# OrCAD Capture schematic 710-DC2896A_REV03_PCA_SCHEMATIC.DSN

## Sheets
1 PAGE1: size Custom; company: ANALOG DEVICES; note: DEMO BOARD BILL OF MATERIALS; note: MULTIPHASE BOOST CONVERTER EXPANDER WITH INTERNAL GATE DRIVERS
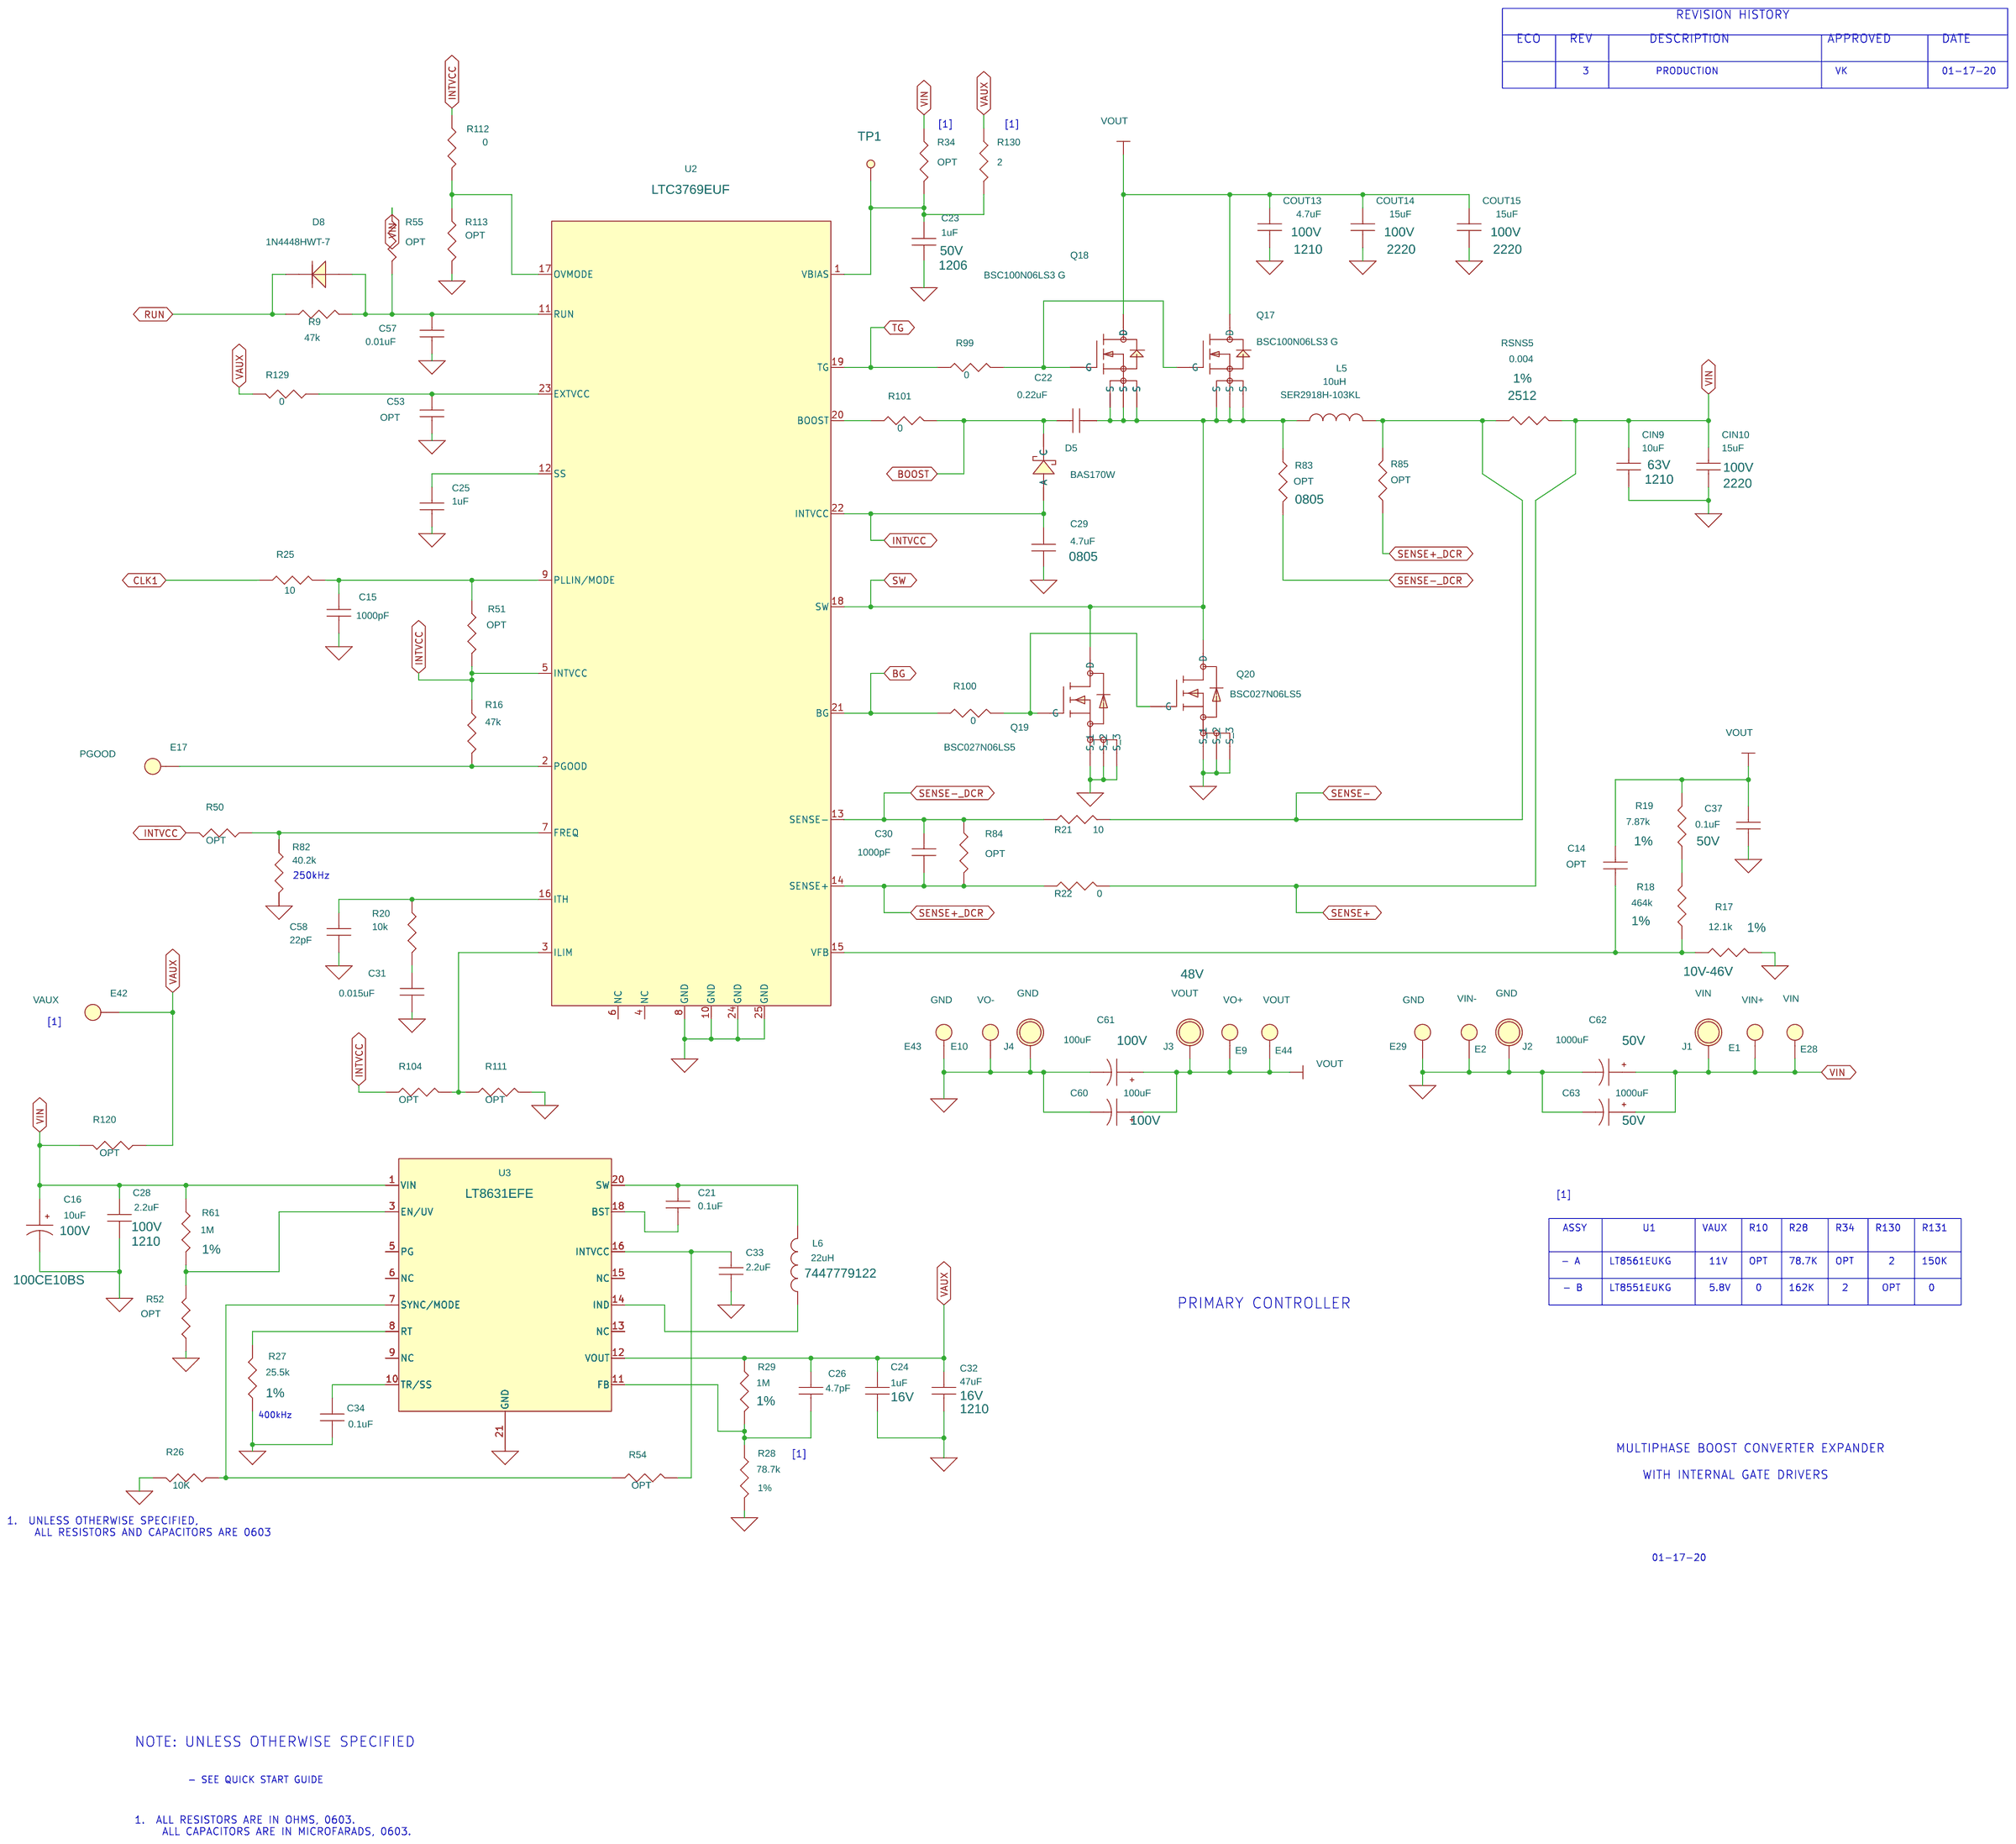
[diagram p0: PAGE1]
2 PAGE2: size Custom
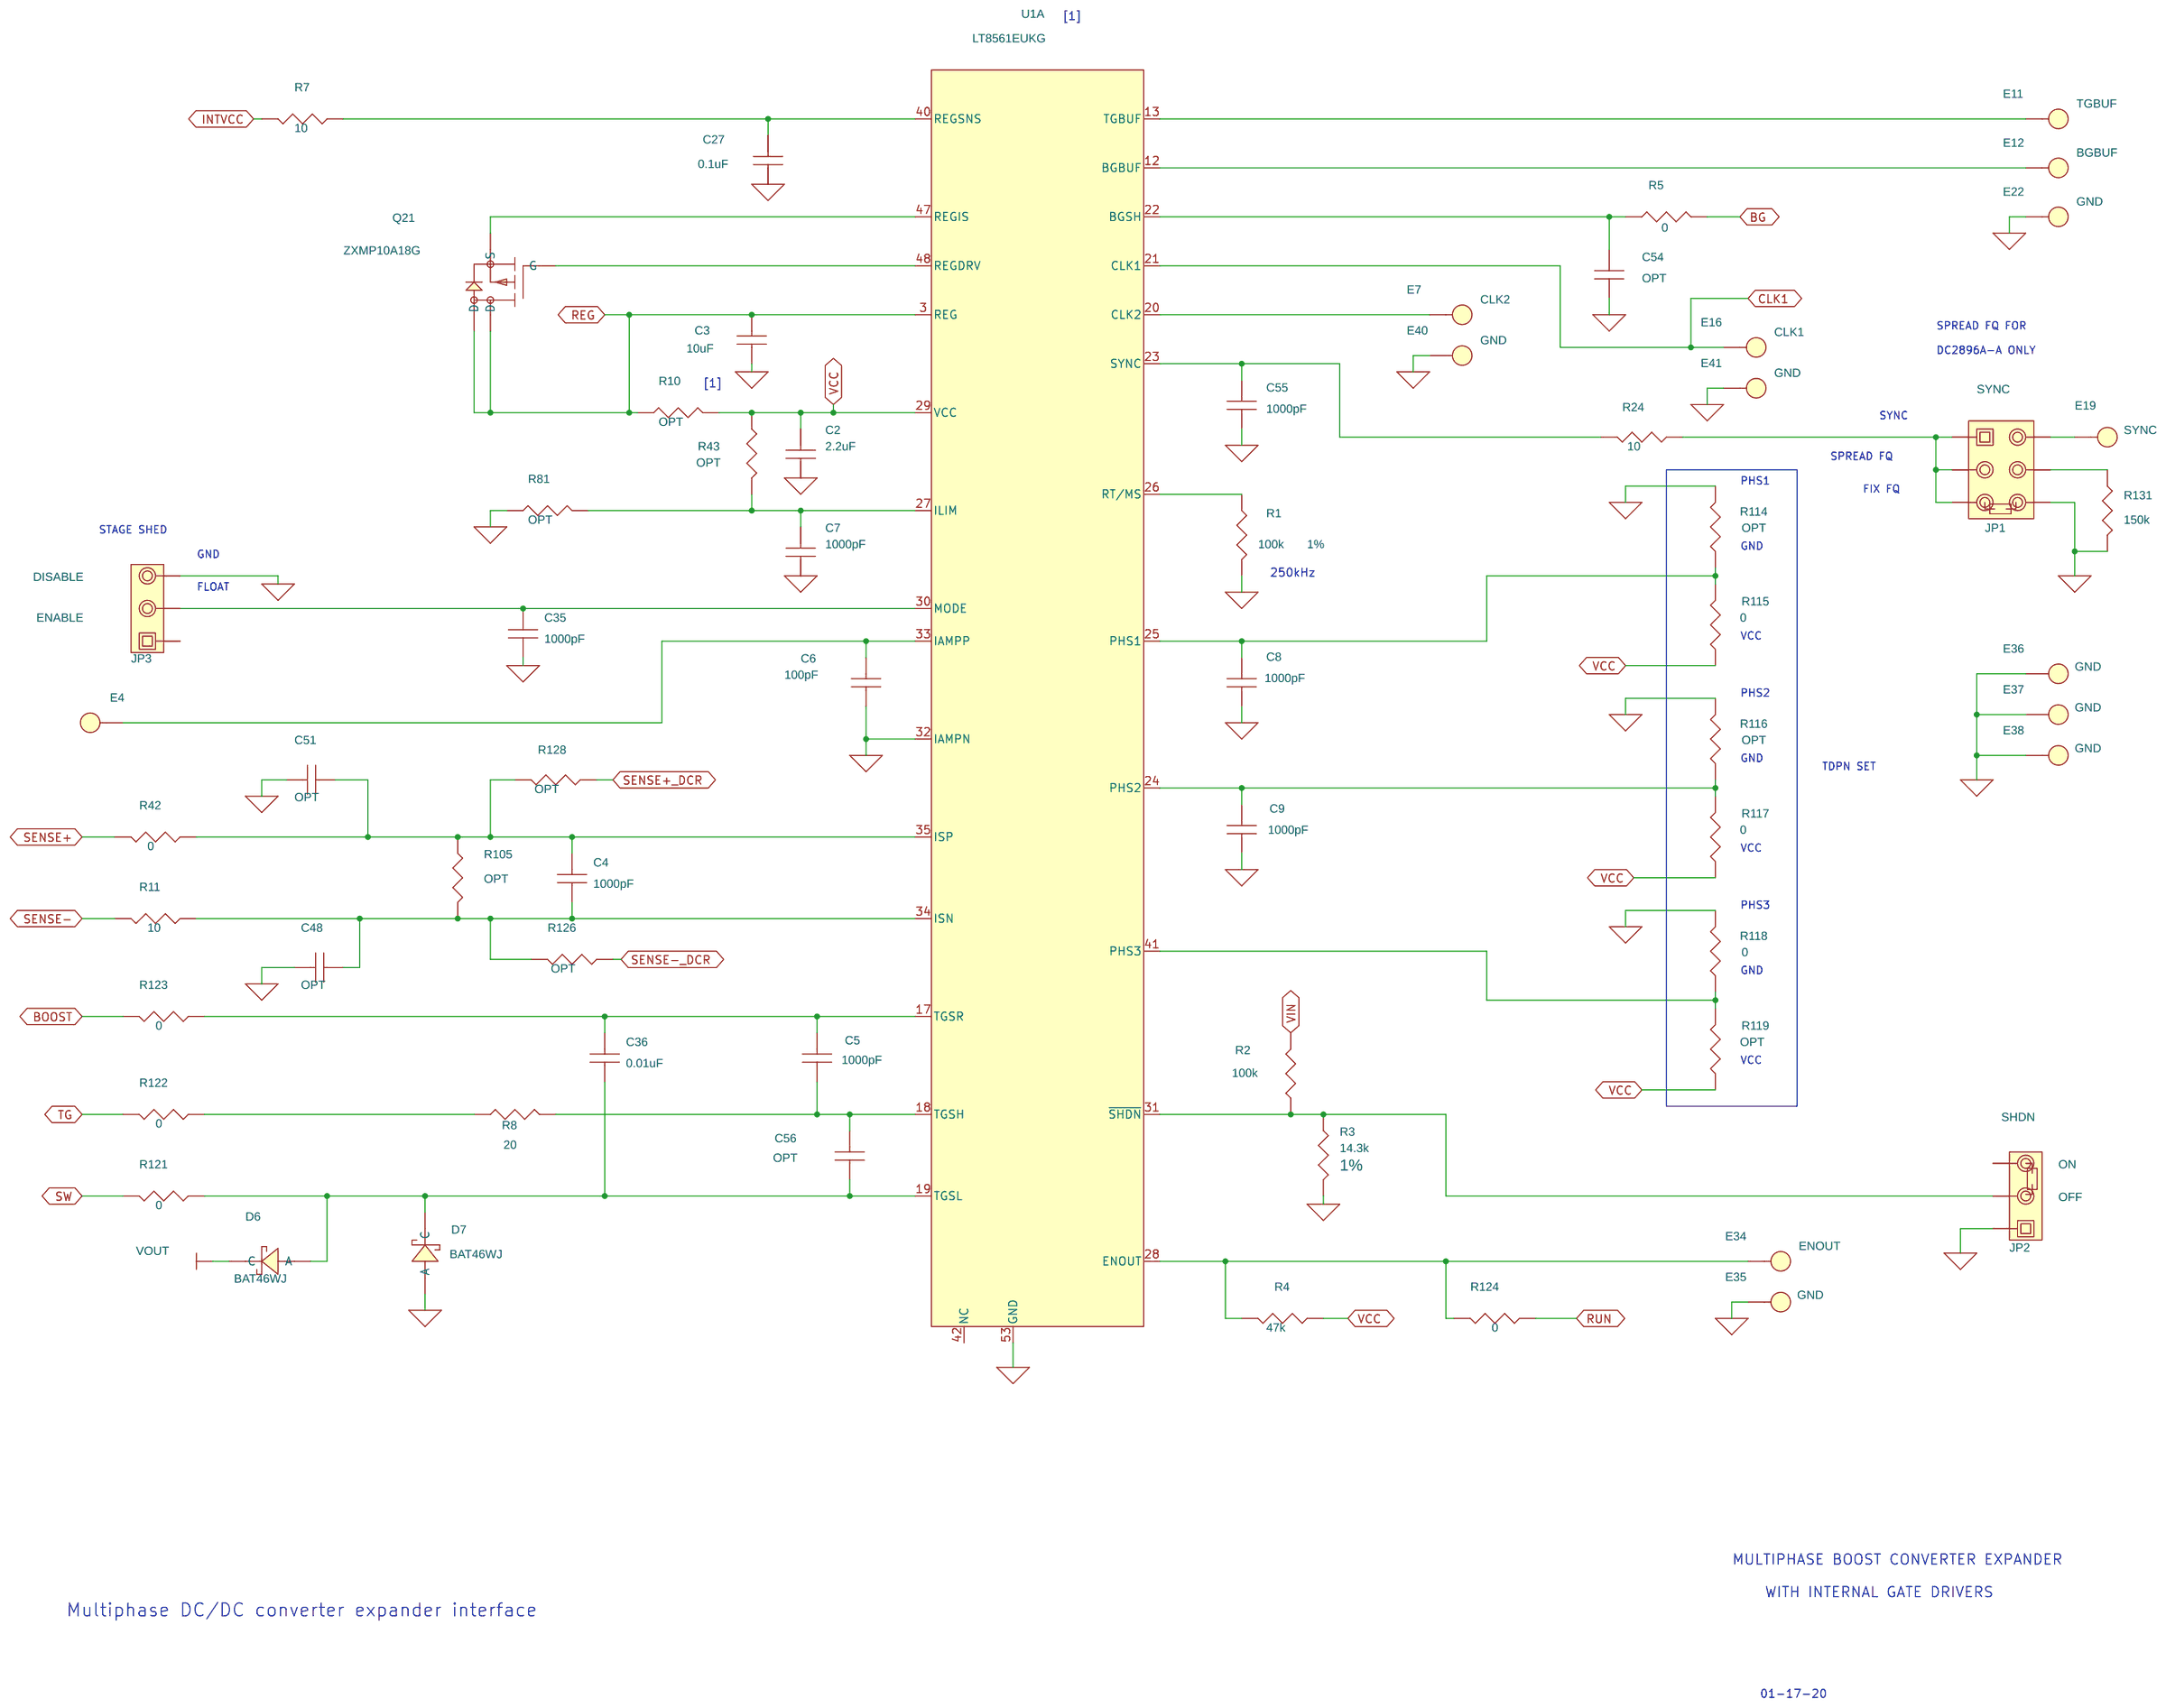
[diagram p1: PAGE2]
3 PAGE4: size Custom
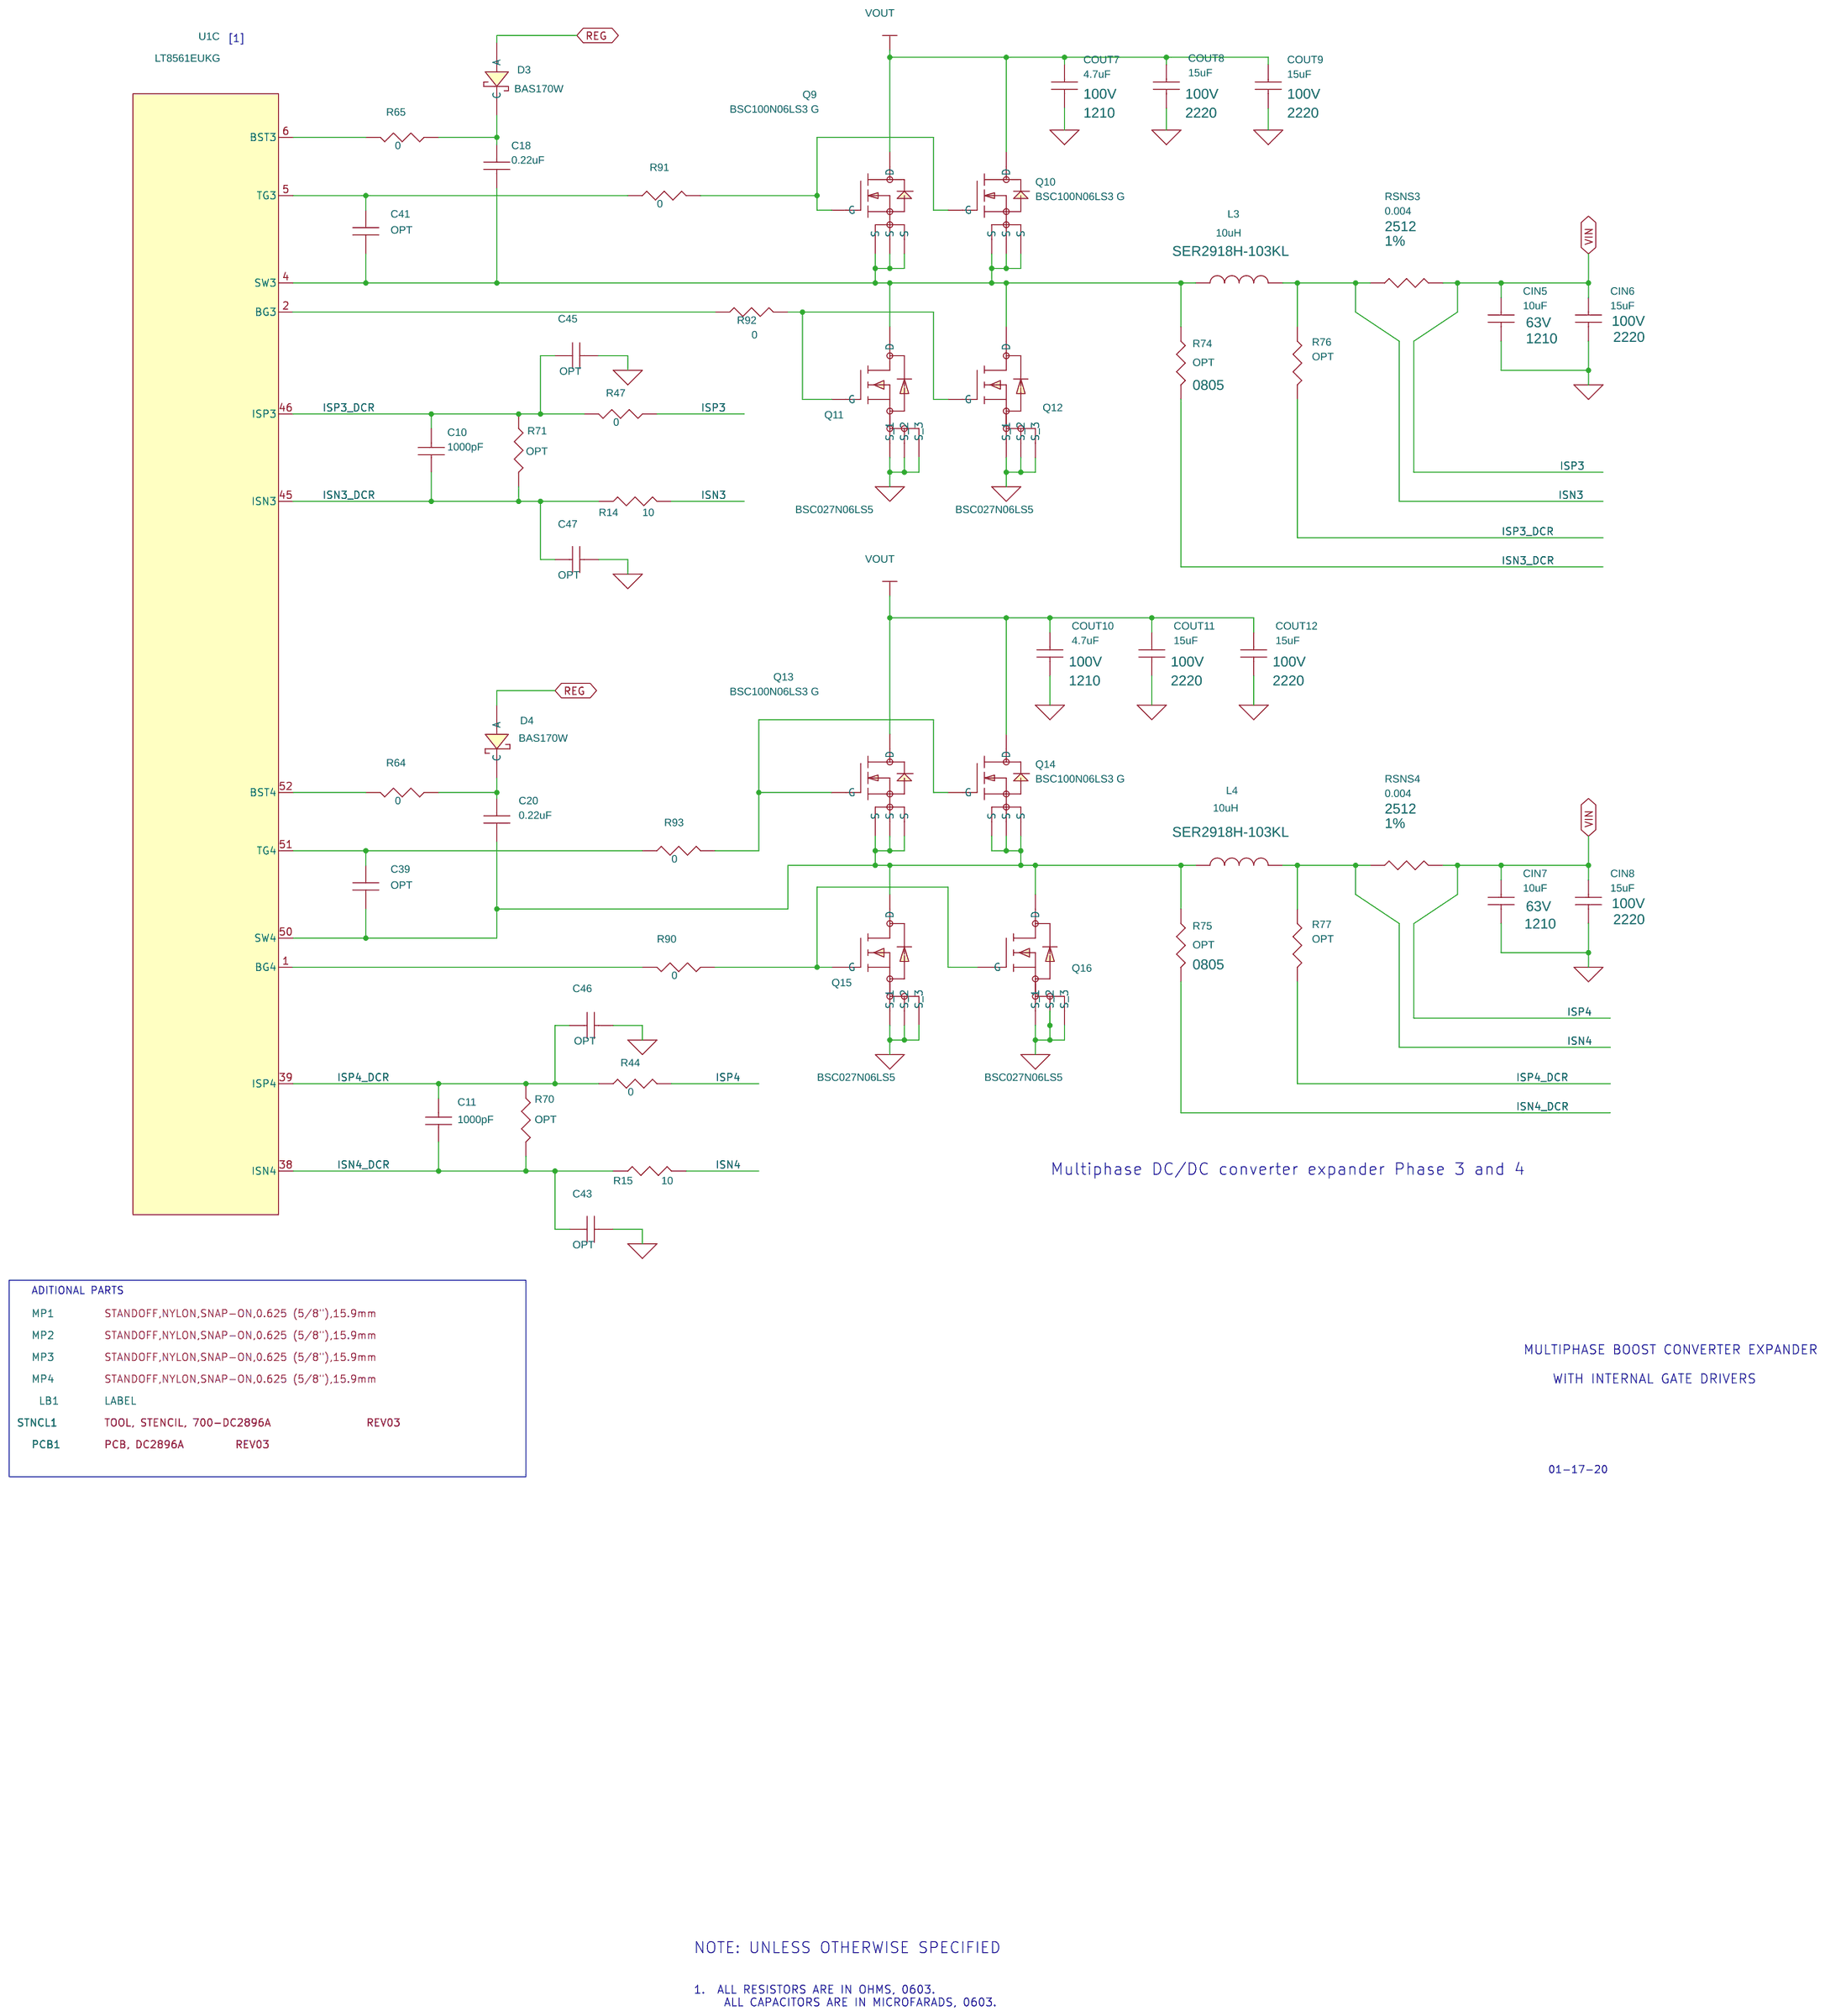
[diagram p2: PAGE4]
4 PAGE3: size Custom
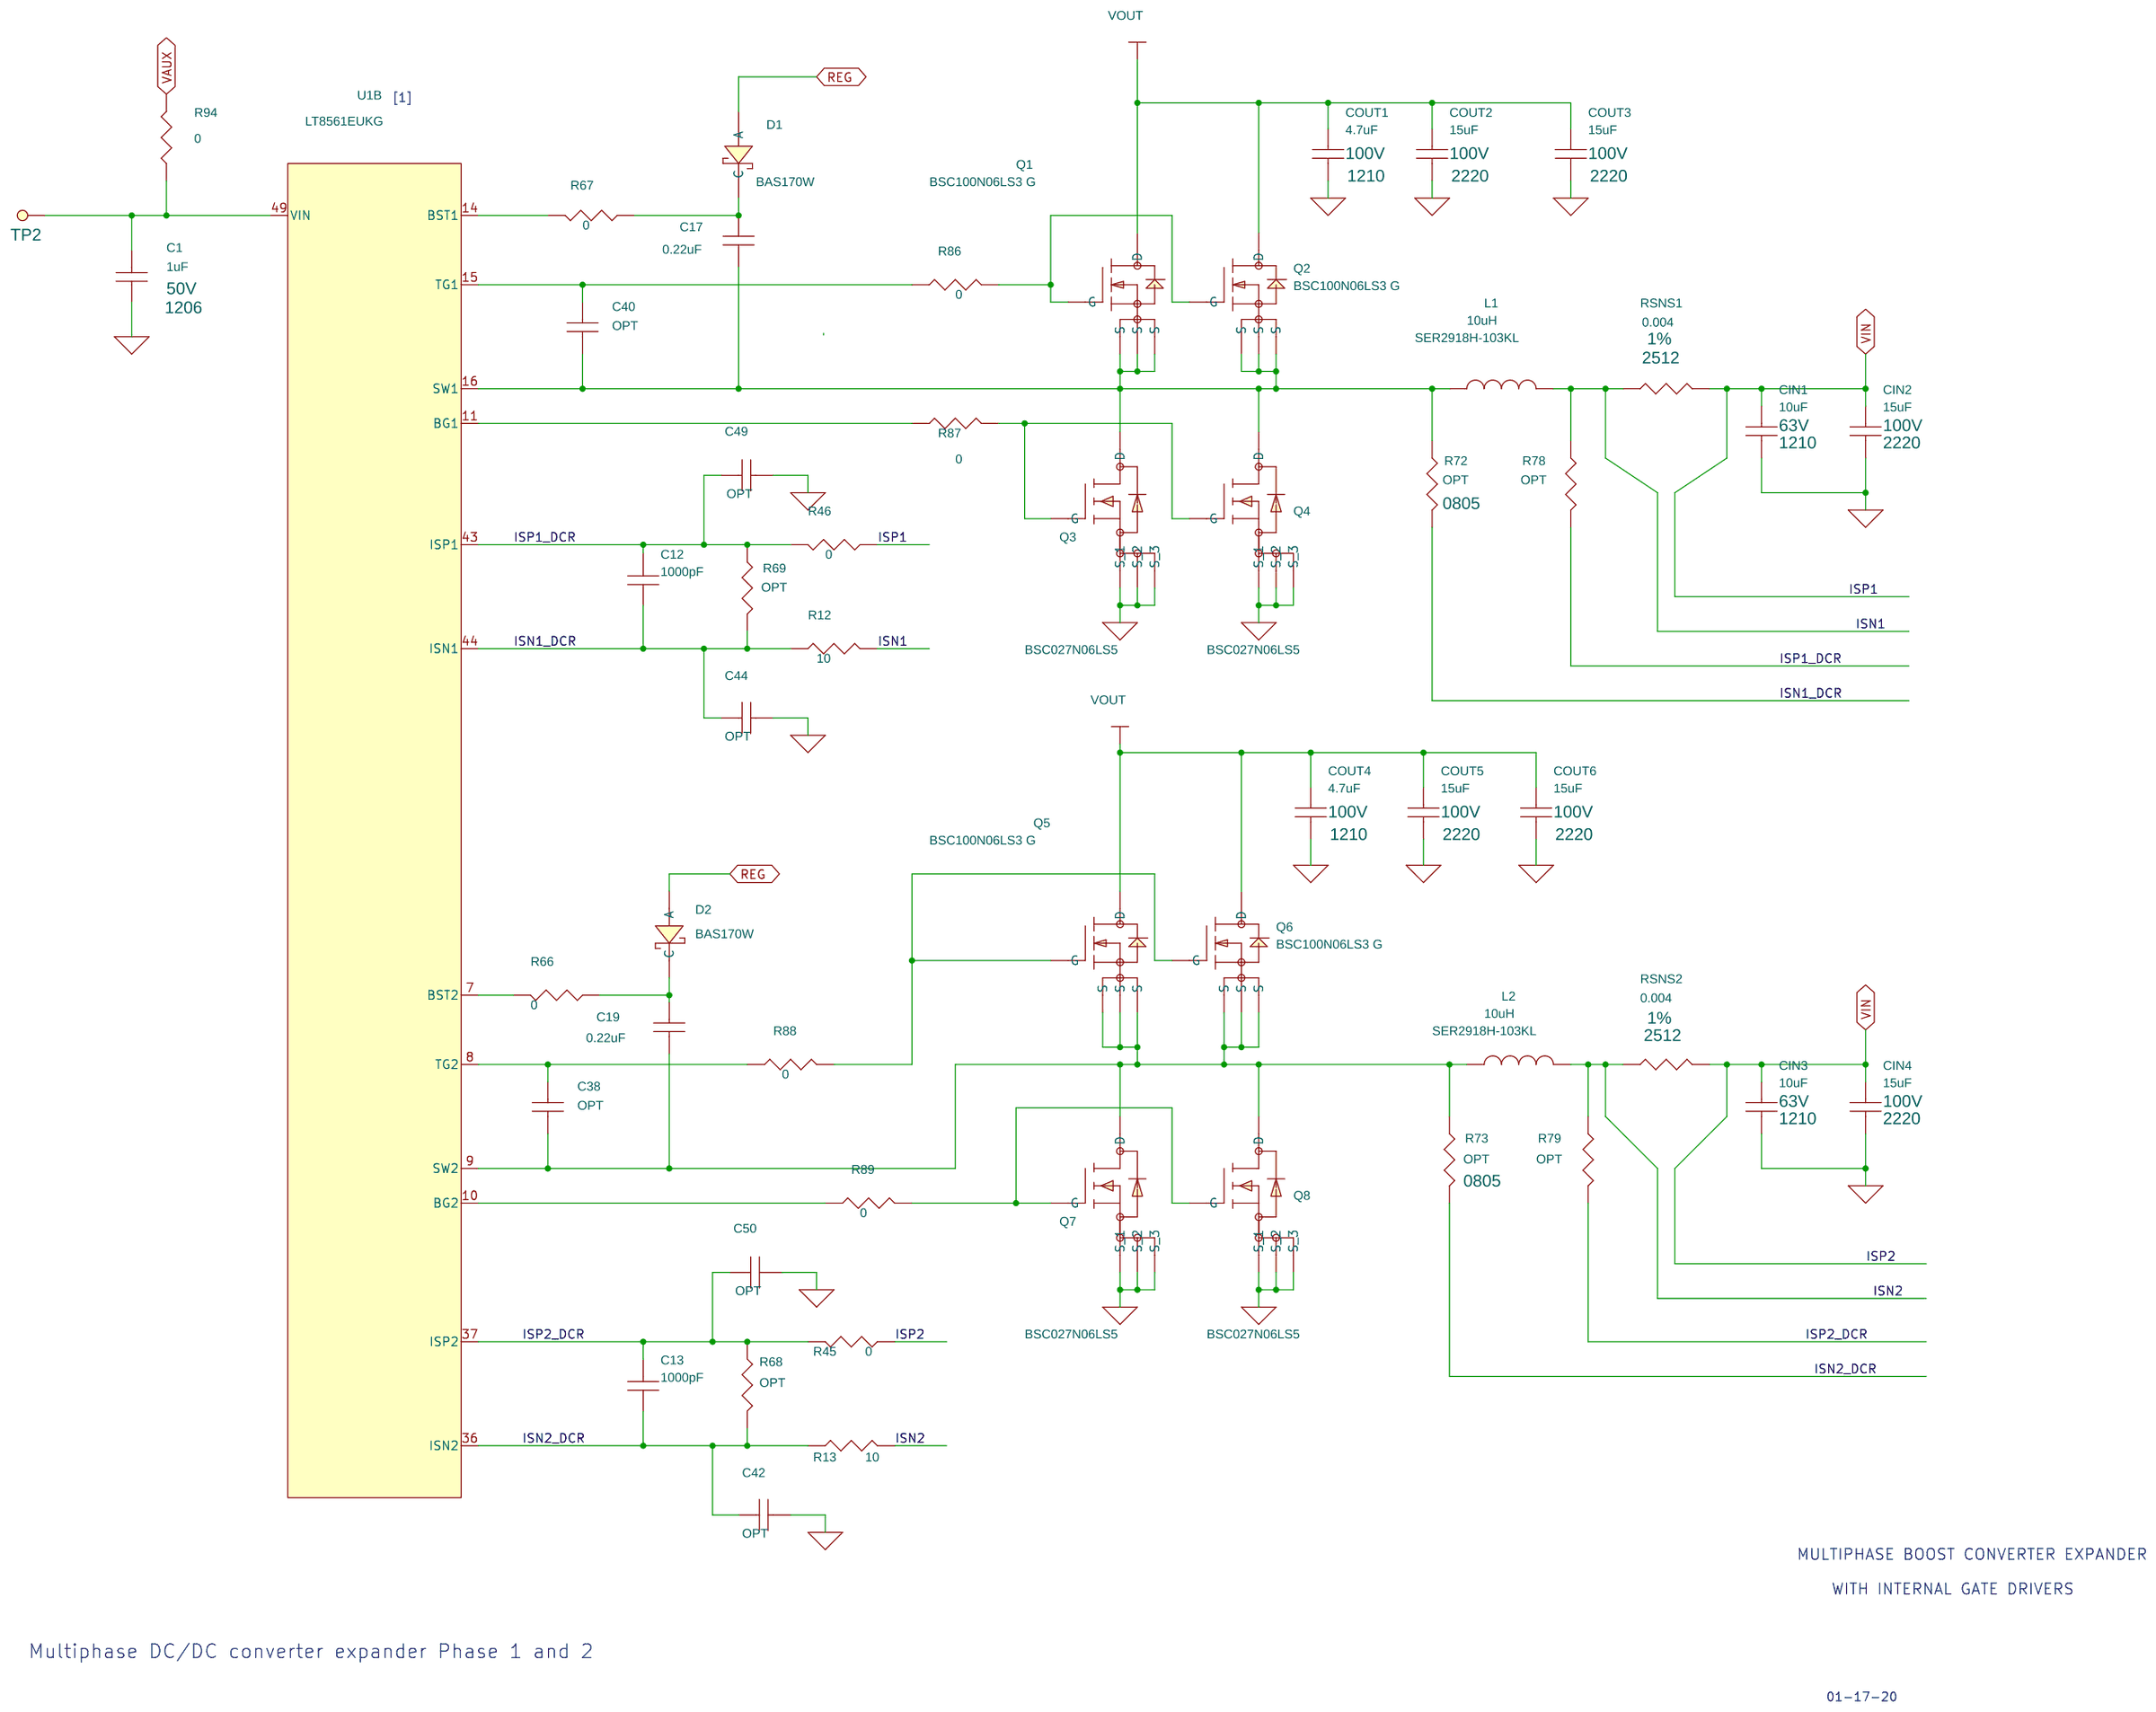
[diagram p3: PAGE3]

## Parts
sheet PAGE1
C14  OPT  [CC0603N]
C15  1000pF  [CC0603N]
C16  10uF  [SUNCON_CE-BS_6.3X7.7]
C21  0.1uF  [CC0603N]
C22  0.22uF  [CC0603N]
C23  1uF  [CC1206N]
C24  1uF  [CC0603N]
C25  1uF  [CC0603N]
C26  4.7pF  [CC0603N]
C28  2.2uF  [CC1210N]
C29  4.7uF  [CC0805N]
C30  1000pF  [CC0603N]
C31  0.015uF  [CC0603N]
C32  47uF  [CC1210N]
C33  2.2uF  [CC0603N]
C34  0.1uF  [CC0603N]
C37  0.1uF  [CC0603N]
C53  OPT  [CC0603N]
C57  0.01uF  [CC0603N]
C58  22pF  [CC0603N]
C60  100uF  [SUNCON_CE-BS_16X16.5]
C61  100uF  [SUNCON_CE-BS_16X16.5]
C62  1000uF  [PANASONIC_FKV_16X16.5]
C63  1000uF  [PANASONIC_FKV_16X16.5]
CIN9  10uF  [CC1210N]
CIN10  15uF  [CC2220N]
COUT13  4.7uF  [CC1210N]
COUT14  15uF  [CC2220N]
COUT15  15uF  [CC2220N]
D5  BAS170W  [SOD-323N]
D8  1N4448HWT-7  [SOD-523N]
E1  TEST POINT  [MILLMAX2308]
E2  TEST POINT  [MILLMAX2308]
E9  TEST POINT  [MILLMAX2308]
E10  TEST POINT  [MILLMAX2308]
E17  TEST POINT  [MILLMAX2308]
E28  TEST POINT  [MILLMAX2308]
E29  TEST POINT  [MILLMAX2308]
E42  TEST POINT  [MILLMAX2308]
E43  TEST POINT  [MILLMAX2308]
E44  TEST POINT  [MILLMAX2308]
J1  STUD,#10-32  [PENN-KFH-032]
J2  STUD,#10-32  [PENN-KFH-032]
J3  STUD,#10-32  [PENN-KFH-032]
J4  STUD,#10-32  [PENN-KFH-032]
L5  10uH  [COILCRAFT-SER2900]
L6  22uH  [WURTH-7345]
Q17  BSC100N06LS3 G  [INFINEON-PG-TDSON-8]
Q18  BSC100N06LS3 G  [INFINEON-PG-TDSON-8]
Q19  BSC027N06LS5  [INFINEON-PG-TDSON-8]
Q20  BSC027N06LS5  [INFINEON-PG-TDSON-8]
R9  47k  [CR0603N]
R16  47k  [CR0603N]
R17  12.1k  [CR0603N]
R18  464k  [CR0603N]
R19  7.87k  [CR0603N]
R20  10k  [CR0603N]
R21  10  [CR0603N]
R22  0  [CR0603N]
R25  10  [CR0603N]
R26  10K  [CR0603N]
R27  25.5k  [CR0603N]
R28  78.7k  [CR0603N]
R29  1M  [CR0603N]
R34  OPT  [CR0603N]
R50  OPT  [CR0603N]
R51  OPT  [CR0603N]
R52  OPT  [CR0603N]
R54  OPT  [CR0603N]
R55  OPT  [CR0603N]
R61  1M  [CR0603N]
R82  40.2k  [CR0603N]
R83  OPT  [CR0805N]
R84  OPT  [CR0603N]
R85  OPT  [CR0603N]
R99  0  [CR0603N]
R100  0  [CR0603N]
R101  0  [CR0603N]
R104  OPT  [CR0603N]
R111  OPT  [CR0603N]
R112  0  [CR0603N]
R113  OPT  [CR0603N]
R120  OPT  [CR0603N]
R129  0  [CR0603N]
R130  2  [CR0603N]
RSNS5  0.004  [PANASONIC-ERJMS4S]
TP1  TP3  [TEST-PIN]
U2  LTC3769-UF  [LTC-UF-24-1697]
U3  LT8631-FE  [LTC-FE-20-1924(CB)]
sheet PAGE2
C2  2.2uF  [CC0603N]
C3  10uF  [CC0603N]
C4  1000pF  [CC0603N]
C5  1000pF  [CC0603N]
C6  100pF  [CC0603N]
C7  1000pF  [CC0603N]
C8  1000pF  [CC0603N]
C9  1000pF  [CC0603N]
C27  0.1uF  [CC0603N]
C35  1000pF  [CC0603N]
C36  0.01uF  [CC0603N]
C48  OPT  [CC0603N]
C51  OPT  [CC0603N]
C54  OPT  [CC0603N]
C55  1000pF  [CC0603N]
C56  OPT  [CC0603N]
D6  BAT46WJ  [SOD-323F-N]
D7  BAT46WJ  [SOD-323F-N]
E4  TEST POINT  [MILLMAX2308]
E7  TEST POINT  [MILLMAX2308]
E11  TEST POINT  [MILLMAX2308]
E12  TEST POINT  [MILLMAX2308]
E16  TEST POINT  [MILLMAX2308]
E19  TEST POINT  [MILLMAX2308]
E22  TEST POINT  [MILLMAX2308]
E34  TEST POINT  [MILLMAX2308]
E35  TEST POINT  [MILLMAX2308]
E36  TEST POINT  [MILLMAX2308]
E37  TEST POINT  [MILLMAX2308]
E38  TEST POINT  [MILLMAX2308]
E40  TEST POINT  [MILLMAX2308]
E41  TEST POINT  [MILLMAX2308]
JP1  HDR.  [HD2X3-079]
JP2  HDR  [HD1X3-079]
JP3  HDR  [HD1X3-079]
Q21  ZXMP10A18G  [SOT223-4N]
R1  100k  [CR0603N]
R2  100k  [CR0603N]
R3  14.3k  [CR0603N]
R4  47k  [CR0603N]
R5  0  [CR0603N]
R7  10  [CR0603N]
R8  20  [CR0603N]
R10  OPT  [CR0603N]
R11  10  [CR0603N]
R24  10  [CR0603N]
R42  0  [CR0603N]
R43  OPT  [CR0603N]
R81  OPT  [CR0603N]
R105  OPT  [CR0603N]
R114  OPT  [CR0603N]
R115  0  [CR0603N]
R116  OPT  [CR0603N]
R117  0  [CR0603N]
R118  0  [CR0603N]
R119  OPT  [CR0603N]
R121  0  [CR0603N]
R122  0  [CR0603N]
R123  0  [CR0603N]
R124  0  [CR0603N]
R126  OPT  [CR0603N]
R128  OPT  [CR0603N]
R131  150k  [CR0603N]
XJP1  SHUNT
XJP2  SHUNT
XJP3  SHUNT
sheet PAGE3
C1  1uF  [CC1206N]
C12  1000pF  [CC0603N]
C13  1000pF  [CC0603N]
C17  0.22uF  [CC0603N]
C19  0.22uF  [CC0603N]
C38  OPT  [CC0603N]
C40  OPT  [CC0603N]
C42  OPT  [CC0603N]
C44  OPT  [CC0603N]
C49  OPT  [CC0603N]
C50  OPT  [CC0603N]
CIN1  10uF  [CC1210N]
CIN2  15uF  [CC2220N]
CIN3  10uF  [CC1210N]
CIN4  15uF  [CC2220N]
COUT1  4.7uF  [CC1210N]
COUT2  15uF  [CC2220N]
COUT3  15uF  [CC2220N]
COUT4  4.7uF  [CC1210N]
COUT5  15uF  [CC2220N]
COUT6  15uF  [CC2220N]
D1  BAS170W  [SOD-323N]
D2  BAS170W  [SOD-323N]
L1  10uH  [COILCRAFT-SER2900]
L2  10uH  [COILCRAFT-SER2900]
Q1  BSC100N06LS3 G  [INFINEON-PG-TDSON-8]
Q2  BSC100N06LS3 G  [INFINEON-PG-TDSON-8]
Q3  BSC027N06LS5  [INFINEON-PG-TDSON-8]
Q4  BSC027N06LS5  [INFINEON-PG-TDSON-8]
Q5  BSC100N06LS3 G  [INFINEON-PG-TDSON-8]
Q6  BSC100N06LS3 G  [INFINEON-PG-TDSON-8]
Q7  BSC027N06LS5  [INFINEON-PG-TDSON-8]
Q8  BSC027N06LS5  [INFINEON-PG-TDSON-8]
R12  10  [CR0603N]
R13  10  [CR0603N]
R45  0  [CR0603N]
R46  0  [CR0603N]
R66  0  [CR0603N]
R67  0  [CR0603N]
R68  OPT  [CR0603N]
R69  OPT  [CR0603N]
R72  OPT  [CR0805N]
R73  OPT  [CR0805N]
R78  OPT  [CR0603N]
R79  OPT  [CR0603N]
R86  0  [CR0603N]
R87  0  [CR0603N]
R88  0  [CR0603N]
R89  0  [CR0603N]
R94  0  [CR0603N]
RSNS1  0.004  [PANASONIC-ERJMS4S]
RSNS2  0.004  [PANASONIC-ERJMS4S]
TP2  VIN-TP  [TEST-PIN]
U1  LT8561-UKG  [LTC-UKG-52-1729]  (sections A,B,C)
sheet PAGE4
C10  1000pF  [CC0603N]
C11  1000pF  [CC0603N]
C18  0.22uF  [CC0603N]
C20  0.22uF  [CC0603N]
C39  OPT  [CC0603N]
C41  OPT  [CC0603N]
C43  OPT  [CC0603N]
C45  OPT  [CC0603N]
C46  OPT  [CC0603N]
C47  OPT  [CC0603N]
CIN5  10uF  [CC1210N]
CIN6  15uF  [CC2220N]
CIN7  10uF  [CC1210N]
CIN8  15uF  [CC2220N]
COUT7  4.7uF  [CC1210N]
COUT8  15uF  [CC2220N]
COUT9  15uF  [CC2220N]
COUT10  4.7uF  [CC1210N]
COUT11  15uF  [CC2220N]
COUT12  15uF  [CC2220N]
D3  BAS170W  [SOD-323N]
D4  BAS170W  [SOD-323N]
L3  10uH  [COILCRAFT-SER2900]
L4  10uH  [COILCRAFT-SER2900]
LB1  LABEL  [895-0154_REV01]
MP1  STANDOFF  [KEYSTONE_8829-8834]
MP2  STANDOFF  [KEYSTONE_8829-8834]
MP3  STANDOFF  [KEYSTONE_8829-8834]
MP4  STANDOFF  [KEYSTONE_8829-8834]
PCB1  PCB, DC2896A  [MECHANICAL_PART]
Q9  BSC100N06LS3 G  [INFINEON-PG-TDSON-8]
Q10  BSC100N06LS3 G  [INFINEON-PG-TDSON-8]
Q11  BSC027N06LS5  [INFINEON-PG-TDSON-8]
Q12  BSC027N06LS5  [INFINEON-PG-TDSON-8]
Q13  BSC100N06LS3 G  [INFINEON-PG-TDSON-8]
Q14  BSC100N06LS3 G  [INFINEON-PG-TDSON-8]
Q15  BSC027N06LS5  [INFINEON-PG-TDSON-8]
Q16  BSC027N06LS5  [INFINEON-PG-TDSON-8]
R14  10  [CR0603N]
R15  10  [CR0603N]
R44  0  [CR0603N]
R47  0  [CR0603N]
R64  0  [CR0603N]
R65  0  [CR0603N]
R70  OPT  [CR0603N]
R71  OPT  [CR0603N]
R74  OPT  [CR0805N]
R75  OPT  [CR0805N]
R76  OPT  [CR0603N]
R77  OPT  [CR0603N]
R90  0  [CR0603N]
R91  0  [CR0603N]
R92  0  [CR0603N]
R93  0  [CR0603N]
RSNS3  0.004  [PANASONIC-ERJMS4S]
RSNS4  0.004  [PANASONIC-ERJMS4S]
STNCL1  TOOL, STENCIL, 700-DC2896A

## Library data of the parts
C14 C38-C51 C53 C54 C56 = CAP: CAP., OPTION, 0603; CLASS: DISCRETE; FPLIST: CC0603N,CC0603L,CC0603M; PART_NUMBER: 150-3038; Package Size: 0603; Package Type: SMD
C4 C5 C7-C13 C15 C30 C35 C55 = CAP: CAP.,1000pF,X7R,25V,10%,0603; CLASS: DISCRETE; Dielectric Type: X7R; FPLIST: CC0603N,CC0603L,CC0603M; Inventory Qty: 115717; Manufacturer: AVX; Manufacturer PN: 06033C102KAT2A; PART_NUMBER: 150-0050; Package Size: 0603; Rated Voltage: 25V; Tolerance: 10%
C16 = CAP_P: CAP.,10uF,ALUM. ELECT.,100V,20%,6.3x7.7; CLASS: DISCRETE; Dielectric Type: ALUM. ELECT.; Inventory Qty: 24; Manufacturer: SUN ELECTRONIC INDUSTRIES CORP; Manufacturer PN: 100CE10BS; PART_NUMBER: 150-3054; Package Size: 6.3x7.7; Rated Voltage: 100V; Tolerance: 20%
C21 C27 C34 C37 = CAP: CAP.,0.1uF,X7R,50V,10%,0603; CLASS: DISCRETE; Dielectric Type: X7R; FPLIST: CC0603N,CC0603L,CC0603M; Inventory Qty: 32641; Manufacturer: AVX; Manufacturer PN: 06035C104KAT2A; PART_NUMBER: 150-0102; Package Size: 0603; Rated Voltage: 50V; Tolerance: 10%
C17-C20 C22 = CAP: CAP.,0.22uF,X5R,16V,10%,0603; CLASS: DISCRETE; Dielectric Type: X5R; FPLIST: CC0603N,CC0603L,CC0603M; Inventory Qty: 0; Manufacturer: AVX; Manufacturer PN: 0603YD224KAT2A; PART_NUMBER: 150-3072; Package Size: 0603; Rated Voltage: 16V; Tolerance: 10%
C1 C23 = CAP: CAP.,1uF,X7R,50V,10%,1206; CLASS: DISCRETE; Dielectric Type: X7R; FPLIST: CC1206N,CC1206L,CC1206M; Inventory Qty: 4219; Manufacturer: AVX; Manufacturer PN: 12065C105KAT2A; PART_NUMBER: 150-3089; Package Size: 1206; Rated Voltage: 50V; Tolerance: 10%
C24 = CAP: CAP.,1uF,X7R,16V,10%,0603; CLASS: DISCRETE; Dielectric Type: X7R; FPLIST: CC0603N,CC0603L,CC0603M; Inventory Qty: 45494; Manufacturer: AVX; Manufacturer PN: 0603YC105KAT2A; PART_NUMBER: 150-3384; Package Size: 0603; Package Type: SMD; Rated Voltage: 16V; Tolerance: 10%
C25 = CAP: CAP.,1uF,X5R,25V,10%,0603; CLASS: DISCRETE; Dielectric Type: X5R; FPLIST: CC0603N,CC0603L,CC0603M; Inventory Qty: 17650; Manufacturer: AVX; Manufacturer PN: 06033D105KAT2A; PART_NUMBER: 150-3069; Package Size: 0603; Rated Voltage: 25V; Tolerance: 10%
C26 = CAP: CAP.,4.7pF,C0G,25V,10%,0603; CLASS: DISCRETE; Dielectric Type: C0G; FPLIST: CC0603N,CC0603L,CC0603M; Inventory Qty: 24942; Manufacturer: AVX; Manufacturer PN: 06033A4R7KAT2A; PART_NUMBER: 150-0381; Package Size: 0603; Rated Voltage: 25V; Tolerance: 10%
C28 = CAP: CAP.,2.2uF,X7R,100V,10%,1210; CLASS: DISCRETE; Dielectric Type: X7R; FPLIST: CC1210N,CC1210L,CC1210M; Inventory Qty: 50196; Manufacturer: MURATA; Manufacturer PN: GRM32ER72A225KA35L; PART_NUMBER: 150-3049; Package Size: 1210; Rated Voltage: 100V; Tolerance: 10%
C29 = CAP: CAP.,4.7uF,X7R,25V,10%,0805; CLASS: DISCRETE; Dielectric Type: X7R; FPLIST: CC0805N,CC0805L,CC0805M; Inventory Qty: 18207; Manufacturer: AVX; Manufacturer PN: 08053C475KAT2A; PART_NUMBER: 150-3337; Package Size: 0805; Rated Voltage: 25V; Tolerance: 10%
C31 = CAP: CAP.,0.015uF,X7R,25V,10%,0603; CLASS: DISCRETE; Dielectric Type: X7R; FPLIST: CC0603N,CC0603L,CC0603M; Inventory Qty: 32248; Manufacturer: AVX; Manufacturer PN: 06033C153KAT2A; PART_NUMBER: 150-3277; Package Size: 0603; Rated Voltage: 25V; Tolerance: 10%
C32 = CAP: CAP.,47uF,X5R,16V,20%,1210; CLASS: DISCRETE; Dielectric Type: X5R; FPLIST: CC1210N,CC1210L,CC1210M; Inventory Qty: 344; Manufacturer: AVX; Manufacturer PN: 1210YD476MAT2A; PART_NUMBER: 150-2441; Package Size: 1210; Package Type: Surface Mount, MLCC; Rated Voltage: 16V; Temperature Coefficient: X7R; Tolerance: 20%
C2 C33 = CAP: CAP.,2.2uF,X5R,25V,10%,0603; CLASS: DISCRETE; Dielectric Type: X5R; FPLIST: CC0603N,CC0603L,CC0603M; Inventory Qty: 27040; Manufacturer: MURATA; Manufacturer PN: GRM188R61E225KA12D; PART_NUMBER: 150-3289; Package Size: 0603; Rated Voltage: 25V; Tolerance: 10%
C36 C57 = CAP: CAP.,0.01uF,X7R,16V,10%,0603; CLASS: DISCRETE; Dielectric Type: X7R; FPLIST: CC0603N,CC0603L,CC0603M; Inventory Qty: 68852; Manufacturer: AVX; Manufacturer PN: 0603YC103KAT2A; PART_NUMBER: 150-0038; Package Size: 0603; Rated Voltage: 16V; Tolerance: 10%
C58 = CAP: CAP.,22pF,C0G,50V,5%,0603; CLASS: DISCRETE; Dielectric Type: C0G; FPLIST: CC0603N,CC0603L,CC0603M; Inventory Qty: 12263; Manufacturer: AVX; Manufacturer PN: 06035A220JAT2A; PART_NUMBER: 150-2248; Package Size: 0603; Rated Voltage: 50V; Tolerance: 5%
C60 C61 = CAP_P_ALT: CAP.,100uF,ALUM. ELECT.,100V,20%,16x16.5mm SMD,RADIAL,Sn Plating; CLASS: DISCRETE; Dielectric Type: ALUM. ELECT.; Inventory Qty: 600; Manufacturer: SUN ELECTRONIC INDUSTRIES CORP; Manufacturer PN: 100CE100BST; PART_NUMBER: 150-1717; Package Size: 16x16.5mm SMD,RADIAL; Rated Voltage: 100V; Tolerance: 20%
C62 C63 = CAP_P_ALT: CAP.,1000uF,ALUM. ELECT.,50V,20%,16x16.5mm SMD,RADIAL,AEC-Q200; CLASS: DISCRETE; Dielectric Type: ALUM. ELECT.; Inventory Qty: 0; Manufacturer: PANASONIC; Manufacturer PN: EEEFK1H102AM; PART_NUMBER: 150-1718; Package Size: 16x16.5mm SMD,RADIAL; Rated Voltage: 50V; Tolerance: 20%
CIN9 = CAP: CAP.,10uF,X7R,63V,10%,1210; 10th Part Field: KRM55WR; CLASS: DISCRETE; Dielectric Type: X7R; FPLIST: CC1210N,CC1210L,CC1210M; Inventory Qty: 8252; Manufacturer: Murata; Manufacturer PN: GRM32ER71J106KA12L; PART_NUMBER: 150-1321; Package Size: 1210; Rated Voltage: 63V; Tolerance: 10%
CIN10 COUT14 COUT15 = CAP: CAP.,15uF,X7S,100V,20%,2220,AEC-Q200; 10th Part Field: KRM55WR; CLASS: DISCRETE; Dielectric Type: X7S; FPLIST: CC2220N,CC2220L,CC2220M; Inventory Qty: 570; Manufacturer: TDK; Manufacturer PN: CGA9P3X7S2A156M250KB; PART_NUMBER: 150-1559; Package Size: 2220; Package Type: Surface Mount, MLCC; Rated Voltage: 100V; Temperature Coefficient: X7S; Tolerance: 20%
COUT1 COUT4 COUT7 COUT10 COUT13 = CAP: CAP.,4.7uF,X7S,100V,10%,1210; CLASS: DISCRETE; Dielectric Type: X7S; FPLIST: CC1210N,CC1210L,CC1210M; Inventory Qty: 7780; Manufacturer: SAMSUNG; Manufacturer PN: CL32Y475KCVZW6E; PART_NUMBER: 150-2270; Package Size: 1210; Package Type: SMD; Rated Voltage: 100V; Temperature Coefficient: X7S; Tolerance: 10%
D1-D5 = DIODE_SCHOTTKY_A: DIODE,SCHOTTKY,70V,70mA,SOD-323,AEC-Q101; CLASS: DISCRETE; FPLIST: SOD-323N,SOD-323L,SOD-323M; Inventory Qty: 5148; Manufacturer: INFINEON; PART_NUMBER: 210-0413; Package Type: SOD-323; Rated Voltage or Zener Voltage: 70V
D8 = DIODE_A_ALT: DIODE,GP SWITCHING,80V,125mA,SOD523,AEC-Q10X; CLASS: DISCRETE; FPLIST: SOD-523N,SOD-523L,SOD-523M; Inventory Qty: 1990; Manufacturer: DIODES INC.; Max Forward Current or Rated Power: 125mA; PART_NUMBER: 210-0128; Package Size: SC-79, SOD-523; Package Type: SOD523; Rated Voltage or Zener Voltage: 80V
E1 = TEST_POINT_.156_MILL-MAX_2308: TEST POINT,TURRET,0.064" MTG. HOLE,PCB 0.062" THK; CLASS: IO; Inventory Qty: 689313; Label: VIN+; Manufacturer: MILL-MAX; Manufacturer PN: 2308-2-00-80-00-00-07-0; PART_NUMBER: 260-0004
E2 = TEST_POINT_.156_MILL-MAX_2308: TEST POINT,TURRET,0.064" MTG. HOLE,PCB 0.062" THK; CLASS: IO; Inventory Qty: 689313; Label: VIN-; Manufacturer: MILL-MAX; Manufacturer PN: 2308-2-00-80-00-00-07-0; PART_NUMBER: 260-0004
E9 = TEST_POINT_.156_MILL-MAX_2308: TEST POINT,TURRET,0.064" MTG. HOLE,PCB 0.062" THK; CLASS: IO; Inventory Qty: 689313; Label: VO+; Manufacturer: MILL-MAX; Manufacturer PN: 2308-2-00-80-00-00-07-0; PART_NUMBER: 260-0004
E10 = TEST_POINT_.156_MILL-MAX_2308: TEST POINT,TURRET,0.064" MTG. HOLE,PCB 0.062" THK; CLASS: IO; Inventory Qty: 689313; Label: VO-; Manufacturer: MILL-MAX; Manufacturer PN: 2308-2-00-80-00-00-07-0; PART_NUMBER: 260-0004
E17 = TEST_POINT_.156_MILL-MAX_2308: TEST POINT,TURRET,0.064" MTG. HOLE,PCB 0.062" THK; CLASS: IO; Inventory Qty: 689313; Label: PGOOD; Manufacturer: MILL-MAX; Manufacturer PN: 2308-2-00-80-00-00-07-0; PART_NUMBER: 260-0004; TEXT: _____
E28 = TEST_POINT_.156_MILL-MAX_2308: TEST POINT,TURRET,0.064" MTG. HOLE,PCB 0.062" THK; CLASS: IO; Inventory Qty: 689313; Label: VIN; Manufacturer: MILL-MAX; Manufacturer PN: 2308-2-00-80-00-00-07-0; PART_NUMBER: 260-0004
E22 E29 E35-E38 E40 E41 E43 = TEST_POINT_.156_MILL-MAX_2308: TEST POINT,TURRET,0.064" MTG. HOLE,PCB 0.062" THK; CLASS: IO; Inventory Qty: 689313; Label: GND; Manufacturer: MILL-MAX; Manufacturer PN: 2308-2-00-80-00-00-07-0; PART_NUMBER: 260-0004
E42 = TEST_POINT_.156_MILL-MAX_2308: TEST POINT,TURRET,0.064" MTG. HOLE,PCB 0.062" THK; CLASS: IO; Inventory Qty: 689313; Label: VAUX; Manufacturer: MILL-MAX; Manufacturer PN: 2308-2-00-80-00-00-07-0; PART_NUMBER: 260-0004; TEXT: _____
E44 = TEST_POINT_.156_MILL-MAX_2308: TEST POINT,TURRET,0.064" MTG. HOLE,PCB 0.062" THK; CLASS: IO; Inventory Qty: 689313; Label: VOUT; Manufacturer: MILL-MAX; Manufacturer PN: 2308-2-00-80-00-00-07-0; PART_NUMBER: 260-0004
J1 = PEM-KFH_A: EVAL BOARD STUD HARDWARE SET, #10-32; CLASS: DISCRETE; Comments: CONSISTS OF QTY(1) STUD, 769-0012; QTY(1) RING LUG, 769-0013;QTY(2) HEX NUT,BRASS,761-0013; QTY(1) WASHER,#10 LOCK, 762-0021; Label: VIN; Manufacturer: ANALOG DEVICES; Manufacturer PN: 720-0010; PART_FIELD_01: 10V-46V; PART_NUMBER: 720-0010
J2 J4 = PEM-KFH_A: EVAL BOARD STUD HARDWARE SET, #10-32; CLASS: DISCRETE; Comments: CONSISTS OF QTY(1) STUD, 769-0012; QTY(1) RING LUG, 769-0013;QTY(2) HEX NUT,BRASS,761-0013; QTY(1) WASHER,#10 LOCK, 762-0021; Label: GND; Manufacturer: ANALOG DEVICES; Manufacturer PN: 720-0010; PART_NUMBER: 720-0010
J3 = PEM-KFH_A: EVAL BOARD STUD HARDWARE SET, #10-32; CLASS: DISCRETE; Comments: CONSISTS OF QTY(1) STUD, 769-0012; QTY(1) RING LUG, 769-0013;QTY(2) HEX NUT,BRASS,761-0013; QTY(1) WASHER,#10 LOCK, 762-0021; Label: VOUT; Manufacturer: ANALOG DEVICES; Manufacturer PN: 720-0010; PART_FIELD_01: 48V; PART_NUMBER: 720-0010
L1-L5 = IND_ALT: IND.,10uH,PWR,10%,28A,2.86mOHMS,SMD,SHIELDED,AEC-Q200; CLASS: DISCRETE; Inventory Qty: 468; Manufacturer: Coilcraft; Manufacturer PN: SER2918H-103KL; PART_NUMBER: 200-0180; Package Size: SMD; Tolerance: 10%
L6 = IND_ALT: IND.,22uH,PWR,SHIELDED,20%,1.41A,110mOHMS,7345,AEC-Q200; CLASS: DISCRETE; Inventory Qty: 0; Manufacturer: WURTH ELEKTRONIK; Manufacturer PN: 7447779122; PART_NUMBER: 200-0688; Package Size: 7345; Tolerance: 20%
Q1 Q2 Q5 Q6 Q9 Q10 Q13 Q14 Q17 Q18 = 5P_N-CH_TYPE1D: XSTR.,MOSFET,N-CH,60V,50A,PG-TDSON-8; CLASS: DISCRETE; Inventory Qty: 0; Manufacturer: INFINEON; PART_NUMBER: 240-0415; Package Type: PG-TDSON-8; Rated Voltage: 60V
Q3 Q4 Q7 Q8 Q11 Q12 Q15 Q16 Q19 Q20 = 5P_N-CH_TYPE1C: XSTR.,MOSFET,N-CH,60V,100A,PG-TDSON-8; CLASS: DISCRETE; Inventory Qty: 12452; Manufacturer: INFINEON; PART_NUMBER: 240-0323; Package Size: PG-TDSON8; Package Type: PG-TDSON-8; Rated Voltage: 60V
R4 R9 R16 = RES: RES.,47k OHMS,1%,1/10W,0603,AEC-Q200; CLASS: DISCRETE; FPLIST: CR0603N,CR0603L,CR0603M; Inventory Qty: 12438; Manufacturer: NIC; Manufacturer PN: NRC06F4702TRF; PART_NUMBER: 100-2416; Package Size: 0603; Rated Power: 1/10W; Temperature Coefficient: +/-100ppm; Tolerance: 1%
R17 = RES: RES.,12.1k OHMS,1%,1/10W,0603,AEC-Q200; CLASS: DISCRETE; FPLIST: CR0603N,CR0603L,CR0603M; Inventory Qty: 122111; Manufacturer: PANASONIC; Manufacturer PN: ERJ3EKF1212V; PART_NUMBER: 100-2655; Package Size: 0603; Rated Power: 1/10W; Temperature Coefficient: 100ppm/C; Tolerance: 1%
R18 = RES: RES.,464k OHMS,1%,1/10W,0603; CLASS: DISCRETE; FPLIST: CR0603N,CR0603L,CR0603M; Inventory Qty: 8300; Manufacturer: SAMSUNG; Manufacturer PN: RC1608F4643CS; PART_NUMBER: 100-2067; Package Size: 0603; Rated Power: 1/10W; Temperature Coefficient: +/-100PPM; Tolerance: 1%
R19 = RES: RES.,7.87k OHMS,1%,1/10W,0603,AEC-Q200; CLASS: DISCRETE; FPLIST: CR0603N,CR0603L,CR0603M; Inventory Qty: 19775; Manufacturer: PANASONIC; Manufacturer PN: ERJ3EKF7871V; PART_NUMBER: 100-1061; Package Size: 0603; Rated Power: 1/10W; Temperature Coefficient: 100ppm; Tolerance: 1%
R20 = RES: RES.,10k OHMS,1%,1/10W,0603; CLASS: DISCRETE; FPLIST: CR0603N,CR0603L,CR0603M; Inventory Qty: 72397; Manufacturer: VISHAY; Manufacturer PN: CRCW060310K0FKEC; PART_NUMBER: 100-2532; Package Size: 0603; Rated Power: 1/10W; Temperature Coefficient: 100ppm/C; Tolerance: 1%
R7 R11-R15 R21 R24 R25 = RES: RES.,10 OHMS,1%,1/10W,0603; CLASS: DISCRETE; FPLIST: CR0603N,CR0603L,CR0603M; Inventory Qty: 146992; Manufacturer: VISHAY; Manufacturer PN: CRCW060310R0FKEA; PART_NUMBER: 100-2306; Package Size: 0603; Rated Power: 1/10W; Temperature Coefficient: 100ppm/C; Tolerance: 1%
R5 R22 R42 R44-R47 R64-R67 R86-R94 R99-R101 R112 R115 R117 R118 R121-R124 R129 = RES: RES.,0 OHM,1/10W,0603; CLASS: DISCRETE; FPLIST: CR0603N,CR0603L,CR0603M; Inventory Qty: 57550; Manufacturer: BOURNS; Manufacturer PN: CR0603-J/-000ELF; PART_NUMBER: 100-2621; Package Size: 0603; Rated Power: 1/10W
R26 = RES: RES.,10K OHMS,1%,1/10W,0603,AEC-Q200; CLASS: DISCRETE; FPLIST: CR0603N,CR0603L,CR0603M; Inventory Qty: 24755; Manufacturer: PANASONIC; Manufacturer PN: ERJ3EKF1002V; PART_NUMBER: 100-0602; Package Size: 0603; Rated Power: 1/10W; Temperature Coefficient: 100PPM; Tolerance: 1%
R27 = RES: RES.,25.5k OHMS,1%,1/10W,0603,AEC-Q200; CLASS: DISCRETE; FPLIST: CR0603N,CR0603L,CR0603M; Inventory Qty: 23898; Manufacturer: PANASONIC; Manufacturer PN: ERJ3EKF2552V; PART_NUMBER: 100-2944; Package Size: 0603; Rated Power: 1/10W; Temperature Coefficient: 100ppm; Tolerance: 1%
R28 = RES: RES.,78.7k OHMS,1%,1/10W,0603; CLASS: DISCRETE; FPLIST: CR0603N,CR0603L,CR0603M; Inventory Qty: 35000; Manufacturer: NIC; Manufacturer PN: NRC06F7872TRF; PART_NUMBER: 100-0291; Package Size: 0603; Rated Power: 1/10W; Temperature Coefficient: 100ppm/C; Tolerance: 1%
R29 R61 = RES: RES.,1M OHM,1%,1/10W,0603,AEC-Q200; CLASS: DISCRETE; FPLIST: CR0603N,CR0603L,CR0603M; Inventory Qty: 163278; Manufacturer: VISHAY; Manufacturer PN: CRCW06031M00FKEA; PART_NUMBER: 100-0335; Package Size: 0603; Rated Power: 1/10W; Temperature Coefficient: 100ppm; Tolerance: 1%
R10 R34 R43 R50-R52 R54 R55 R68-R71 R76-R79 R81 R84 R85 R104 R105 R111 R113 R114 R116 R119 R120 R126 R128 = RES: RES., OPTION, 0603; CLASS: DISCRETE; FPLIST: CR0603N,CR0603L,CR0603M; PART_NUMBER: 100-2374; Package Size: 0603
R82 = RES: RES.,40.2k OHMS,1%,1/10W,0603,AEC-Q200; CLASS: DISCRETE; FPLIST: CR0603N,CR0603L,CR0603M; Inventory Qty: 48778; Manufacturer: NIC; Manufacturer PN: NRC06F4022TRF; PART_NUMBER: 100-2431; Package Size: 0603; Rated Power: 1/10W; Temperature Coefficient: 100ppm/C; Tolerance: 1%
R72-R75 R83 = RES: RES., OPTION, 0805; CLASS: DISCRETE; FPLIST: CR0805N,CR0805L,CR0805M; PART_NUMBER: 100-2558; Package Size: 0805
R130 = RES: RES.,2 OHMS,1%,1/10W,0603; CLASS: DISCRETE; FPLIST: CR0603N,CR0603L,CR0603M; Inventory Qty: 19237; Manufacturer: VISHAY; Manufacturer PN: CRCW06032R00FNEA; PART_NUMBER: 100-2290; Package Size: 0603; Rated Power: 1/10W; Temperature Coefficient: 200ppm/C; Tolerance: 1%
RSNS1-RSNS5 = RES: RES.,0.004 OHM,1%,3W,2512,METAL,SENSE,AEC-Q200; CLASS: DISCRETE; FPLIST: CR2512N,CR2512L,CR2512M; Inventory Qty: 5274; Manufacturer: PANASONIC; Manufacturer PN: ERJMS4SF4M0U; PART_NUMBER: 100-1023; Package Size: 2512; Rated Power: 3W; Temperature Coefficient: +/-75ppm; Tolerance: 1%
TP1 TP2 = TESTPIN-1_1
U2 = LTC3769-UF: IC,60V Low IQ Synch. Boost Ctrlr.,QFN-24(UF); CLASS: IC; Inventory Qty: 121; LABEL: LTC3769EUF; Manufacturer: LINEAR TECH.; Manufacturer PN: LTC3769EUF#PBF; PART_NUMBER: LTC3769EUF#PBF; Package Size: 4x4; Package Type: QFN-24(UF)
U3 = LT8631-FE: IC,Synch. uPower Step-Down Reg.,TSSOP-20 (FE16),100V,1A; CLASS: IC; Inventory Qty: 462; LABEL: LT8631EFE; Manufacturer: ANALOG DEVICES; Manufacturer PN: LT8631EFE#PBF; PART_NUMBER: LT8631EFE#PBF; Package Size: 16-TSSOP (0.173", 4.40mm Width); Package Type: TSSOP-20 (FE16)
C3 = CAP: CAP.,10uF,X5R,16V,10%,0603; CLASS: DISCRETE; Dielectric Type: X5R; FPLIST: CC0603N,CC0603L,CC0603M; Inventory Qty: 4000; Manufacturer: AVX; Manufacturer PN: 0603YD106KAT2A; PART_NUMBER: 150-2628; Package Size: 0603; Rated Voltage: 16V; Tolerance: 10%
C6 = CAP: CAP.,100pF,X7R,16V,10%,0603; CLASS: DISCRETE; Dielectric Type: X7R; FPLIST: CC0603N,CC0603L,CC0603M; Inventory Qty: 27972; Manufacturer: AVX; Manufacturer PN: 0603YC101KAT2A; PART_NUMBER: 150-0562; Package Size: 0603; Rated Voltage: 16V; Tolerance: 10%
D6 D7 = DIODE_SCHOTTKY_A: DIODE,SCHOTTKY,100V,250mA,SOD-323F,AEC-Q101; CLASS: DISCRETE; FPLIST: SOD-323F-N,SOD-323F-L,SOD-323F-M; Inventory Qty: 7034; Manufacturer: NEXPERIA; Manufacturer PN: BAT46WJ,115; Max Forward Current or Rated Power: 250mA; PART_NUMBER: 210-0235; Package Type: SOD-323F; Rated Voltage or Zener Voltage: 100V
E4 = TEST_POINT_.156_MILL-MAX_2308: TEST POINT,TURRET,0.064" MTG. HOLE,PCB 0.062" THK; CLASS: IO; Inventory Qty: 689313; Label: IAMPP; Manufacturer: MILL-MAX; Manufacturer PN: 2308-2-00-80-00-00-07-0; PART_NUMBER: 260-0004
E7 = TEST_POINT_.156_MILL-MAX_2308: TEST POINT,TURRET,0.064" MTG. HOLE,PCB 0.062" THK; CLASS: IO; Inventory Qty: 689313; Label: CLK2; Manufacturer: MILL-MAX; Manufacturer PN: 2308-2-00-80-00-00-07-0; PART_NUMBER: 260-0004
E11 = TEST_POINT_.156_MILL-MAX_2308: TEST POINT,TURRET,0.064" MTG. HOLE,PCB 0.062" THK; CLASS: IO; Inventory Qty: 689313; Label: TGBUF; Manufacturer: MILL-MAX; Manufacturer PN: 2308-2-00-80-00-00-07-0; PART_NUMBER: 260-0004
E12 = TEST_POINT_.156_MILL-MAX_2308: TEST POINT,TURRET,0.064" MTG. HOLE,PCB 0.062" THK; CLASS: IO; Inventory Qty: 689313; Label: BGBUF; Manufacturer: MILL-MAX; Manufacturer PN: 2308-2-00-80-00-00-07-0; PART_NUMBER: 260-0004
E16 = TEST_POINT_.156_MILL-MAX_2308: TEST POINT,TURRET,0.064" MTG. HOLE,PCB 0.062" THK; CLASS: IO; Inventory Qty: 689313; Label: CLK1; Manufacturer: MILL-MAX; Manufacturer PN: 2308-2-00-80-00-00-07-0; PART_NUMBER: 260-0004
E19 = TEST_POINT_.156_MILL-MAX_2308: TEST POINT,TURRET,0.064" MTG. HOLE,PCB 0.062" THK; CLASS: IO; Inventory Qty: 689313; Label: SYNC; Manufacturer: MILL-MAX; Manufacturer PN: 2308-2-00-80-00-00-07-0; PART_NUMBER: 260-0004
E34 = TEST_POINT_.156_MILL-MAX_2308: TEST POINT,TURRET,0.064" MTG. HOLE,PCB 0.062" THK; CLASS: IO; Inventory Qty: 689313; Label: ENOUT; Manufacturer: MILL-MAX; Manufacturer PN: 2308-2-00-80-00-00-07-0; PART_NUMBER: 260-0004
JP1 = HDR2X3_ALT1: CONN.,HDR.,MALE,2x3,2mm,VERT,ST,THT; 9th Part Field: SYNC; CLASS: IO; Inventory Qty: 17378; Manufacturer: WURTH ELEKTRONIK; Manufacturer PN: 62000621121; PART_NUMBER: 250-0483
JP2 = 1X3_A: CONN.,HDR,MALE,1x3,2mm,VERT,ST,THT,NO SUBS. ALLOWED; 10th Part Field: OFF; 11th Part Field: SHDN; 9th Part Field: ON; CLASS: IO; Inventory Qty: 26902; Manufacturer: Wurth Elektronik; Manufacturer PN: 62000311121; PART_NUMBER: 250-0639
JP3 = 1X3_A: CONN.,HDR,MALE,1x3,2mm,VERT,ST,THT,NO SUBS. ALLOWED; 10th Part Field: ENABLE; 11th Part Field: MODE; 9th Part Field: DISABLE; CLASS: IO; Inventory Qty: 26902; Manufacturer: Wurth Elektronik; Manufacturer PN: 62000311121; PART_NUMBER: 250-0639
Q21 = 4P_P-CH_TYPE1A: XSTR.,MOSFET,P-CH,100V,3.7A,SOT-223-4L,AEC-Q101; CLASS: DISCRETE; Inventory Qty: 995; Manufacturer: DIODES INC.; Manufacturer PN: ZXMP10A18GTA; PART_NUMBER: 240-0416; Package Type: SOT-223-4L; Rated Voltage: 100V
R1 R2 = RES: RES.,100k OHMS,1%,1/10W,0603,AEC-Q200; CLASS: DISCRETE; FPLIST: CR0603N,CR0603L,CR0603M; Inventory Qty: 40600; Manufacturer: PANASONIC; Manufacturer PN: ERJ3EKF1003V; PART_NUMBER: 100-0981; Package Size: 0603; Rated Power: 1/10W; Temperature Coefficient: 100ppm; Tolerance: 1%
R3 = RES: RES.,14.3k OHMS,1%,1/10W,0603,AEC-Q200; CLASS: DISCRETE; Inventory Qty: 10000; Manufacturer: Vishay; Manufacturer PN: CRCW060314K3FKEA; PART_NUMBER: 100-1075; Package Size: 0603; Rated Power: 1/10W; Temperature Coefficient: +/-100ppm; Tolerance: 1%
R8 = RES: RES.,20 OHMS,5%,1/10W,0603,AEC-Q200; CLASS: DISCRETE; FPLIST: CR0603N,CR0603L,CR0603M; Inventory Qty: 19408; Manufacturer: VISHAY; Manufacturer PN: CRCW060320R0JNEA; PART_NUMBER: 100-2401; Package Size: 0603; Rated Power: 1/10W; Temperature Coefficient: 200ppm; Tolerance: 5%
R131 = RES: RES.,150k OHMS,1%,1/10W,0603; CLASS: DISCRETE; FPLIST: CR0603N,CR0603L,CR0603M; Inventory Qty: 37624; Manufacturer: PANASONIC; Manufacturer PN: ERJ3EKF1503V; PART_NUMBER: 100-2438; Package Size: 0603; Rated Power: 1/10W; Temperature Coefficient: 100ppm/C; Tolerance: 1%
XJP1-XJP3 = SHUNT_2MM_C: CONN.,SHUNT,FEMALE,2 POS,2mm; CLASS: IO; Inventory Qty: 72496; Manufacturer: Wurth Elektronik; Manufacturer PN: 60800213421; PART_NUMBER: 250-0485
CIN1 CIN3 CIN5 CIN7 = CAP: CAP.,10uF,X7R,63V,10%,1210; CLASS: DISCRETE; Dielectric Type: X7R; FPLIST: CC1210N,CC1210L,CC1210M; Inventory Qty: 8252; Manufacturer: Murata; Manufacturer PN: GRM32ER71J106KA12L; PART_NUMBER: 150-1321; Package Size: 1210; Rated Voltage: 63V; Tolerance: 10%
CIN2 CIN4 CIN6 CIN8 COUT2 COUT3 COUT5 COUT6 COUT8 COUT9 COUT11 COUT12 = CAP: CAP.,15uF,X7S,100V,20%,2220,AEC-Q200; CLASS: DISCRETE; Dielectric Type: X7S; FPLIST: CC2220N,CC2220L,CC2220M; Inventory Qty: 570; Manufacturer: TDK; Manufacturer PN: CGA9P3X7S2A156M250KB; PART_NUMBER: 150-1559; Package Size: 2220; Package Type: Surface Mount, MLCC; Rated Voltage: 100V; Temperature Coefficient: X7S; Tolerance: 20%
U1 = LT8561_51-UKG: IC,GATE DRIVER BOOST CONVERTERS,QFN-52; CLASS: IC; Inventory Qty: 0; Manufacturer: ANALOG DEVICES; Manufacturer PN: LT8561EUKG#PBF; PART_NUMBER: LT8561EUKG#PBF; Package Size: 7x8mm; Package Type: QFN-52; label: LT8561EUKG
LB1 = BLANK_LABEL: LABEL SPEC, DEMO BOARD SERIAL NUMBER; Inventory Qty: 0; Manufacturer: BRADY; Manufacturer PN: THT-96-717-10; PART_NUMBER: 895-0154
MP1-MP4 = BLANK_PINLESS_MECHANICAL_PART: STANDOFF,NYLON,SNAP-ON,0.625 (5/8"),15.9mm; CLASS: DISCRETE; Inventory Qty: 140789; Manufacturer: KEYSTONE; Manufacturer PN: 8834; PART_NUMBER: 763-0013
PCB1 = BLANK_PCB_PART: BOM Notes: REV03; CLASS: DISCRETE; Inventory Qty: 0; Manufacturer: PHASE 3; Manufacturer PN: 600-DC2896A; PART_NUMBER: 600-DC2896A
STNCL1 = BLANK_STENCIL_PART: BOM Notes: REV03; CLASS: DISCRETE; Inventory Qty: 0; Manufacturer: ANALOG DEVICES; Manufacturer PN: 830-DC2896A; PART_NUMBER: 830-DC2896A

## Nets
GND: C1.1 C2.1 C3.1 C6.1 C7.1 C8.1 C9.1 C15.2 C16.2 C23.1 C24.2 C25.2 C27.1 C28.2 C29.1 C31.2 C32.2 C33.2 C34.2 C35.1 C37.2 C42.2 C43.2 C44.2 C45.2 C46.2 C47.2 C48.2 C49.2 C50.2 C51.2 C53.2 C54.1 C55.1 C57.2 C58.2 C60.2 C61.2 C62.2 C63.2 CIN1.2 CIN2.2 CIN3.2 CIN4.2 CIN5.2 CIN6.2 CIN7.2 CIN8.2 CIN9.2 CIN10.2 COUT1.2 COUT2.2 COUT3.2 COUT4.2 COUT5.2 COUT6.2 COUT7.2 COUT8.2 COUT9.2 COUT10.2 COUT11.2 COUT12.2 COUT13.2 COUT14.2 COUT15.2 D7.2(A) E2.1(A) E10.1(A) E22.1(A) E29.1(A) E35.1(A) E36.1(A) E37.1(A) E38.1(A) E40.1(A) E41.1(A) E43.1(A) J2.1(TP) J4.1(TP) JP1.6 JP2.1 JP3.3 Q3.1(S) Q3.2(S) Q3.3(S) Q4.1(S) Q4.2(S) Q4.3(S) Q7.1(S) Q7.2(S) Q7.3(S) Q8.1(S) Q8.2(S) Q8.3(S) Q11.1(S) Q11.2(S) Q11.3(S) Q12.1(S) Q12.2(S) Q12.3(S) Q15.1(S) Q15.2(S) Q15.3(S) Q16.1(S) Q16.2(S) Q16.3(S) Q19.1(S) Q19.2(S) Q19.3(S) Q20.1(S) Q20.2(S) Q20.3(S) R1.1 R3.1 R17.1 R26.2 R27.1 R28.2 R52.2 R81.2 R82.1 R111.1 R113.1 R114.2 R116.2 R118.2 R131.1 U1.32(IAMPN) U1.53(GND) U2.8(GND) U2.10(GND) U2.24(GND) U2.25(GND) U3.21(GND)
VCC: C2.2 R4.2 R10.1 R43.1 R115.1 R117.1 R119.1 U1.29(VCC)
BG: R5.2 R100.2 U2.21(BG)
BOOST: C22.1 D5.1(C) R101.1 R123.1
CLK1: E16.1(A) R25.2 U1.21(CLK1)
INTVCC: C29.2 D5.2(A) R7.1 R16.2 R50.2 R51.1 R104.2 R112.2 U2.5(INTVCC) U2.22(INTVCC)
ISN1: L1.2 R12.2 R78.1 RSNS1.2
ISN1_DCR: C12.1 C44.1 R12.1 R69.2 R72.2 U1.44(ISN1)
ISN2: L2.2 R13.2 R79.1 RSNS2.2
ISN2_DCR: C13.1 C42.1 R13.1 R68.2 R73.2 U1.36(ISN2)
ISN3: L3.1 R14.2 R76.1 RSNS3.2
ISN3_DCR: C10.1 C47.1 R14.1 R71.2 R74.2 U1.45(ISN3)
ISN4: L4.1 R15.2 R77.1 RSNS4.2
ISN4_DCR: C11.1 C43.1 R15.1 R70.2 R75.2 U1.38(ISN4)
ISP1_DCR: C12.2 C49.1 R46.1 R69.1 R78.2 U1.43(ISP1)
ISP2_DCR: C13.2 C50.1 R45.1 R68.1 R79.2 U1.37(ISP2)
ISP3_DCR: C10.2 C45.1 R47.1 R71.1 R76.2 U1.46(ISP3)
ISP4_DCR: C11.2 C46.1 R44.1 R70.1 R77.2 U1.39(ISP4)
REG: C3.2 D1.2(A) D2.2(A) D3.2(A) D4.2(A) Q21.2(D) Q21.4(D) R10.2 U1.3(REG)
RUN: D8.1(C) R9.2 R124.1
SENSE+: C16.1 C28.1 C62.1 C63.1 CIN1.1 CIN2.1 CIN3.1 CIN4.1 CIN5.1 CIN6.1 CIN7.1 CIN8.1 CIN9.1 CIN10.1 E1.1(A) E28.1(A) J1.1(TP) R2.1 R22.1 R34.2 R42.1 R44.2 R45.2 R46.2 R47.2 R55.2 R61.1 R120.1 RSNS1.1 RSNS2.1 RSNS3.1 RSNS4.1 RSNS5.1 U3.1(VIN)
SENSE+_DCR: C30.2 R22.2 R84.2 R85.2 R128.2 U2.14(SENSE+)
SENSE-: L5.2 R11.1 R21.1 R85.1 RSNS5.2
SENSE-_DCR: C30.1 R21.2 R83.2 R84.1 R126.2 U2.13(SENSE-)
SW: C22.2 L5.1 Q17.1(S) Q17.2(S) Q17.3(S) Q18.1(S) Q18.2(S) Q18.3(S) Q19.5(D) Q20.5(D) R83.1 R121.1 U2.18(SW)
TG: R99.2 R122.1 U2.19(TG)
VAUX: C24.1 C26.1 C32.1 E42.1(A) R29.1 R94.2 R120.2 R129.1 R130.2 U3.12(VOUT)
VOUT: C14.1 C37.1 C60.1 C61.1 COUT1.1 COUT2.1 COUT3.1 COUT4.1 COUT5.1 COUT6.1 COUT7.1 COUT8.1 COUT9.1 COUT10.1 COUT11.1 COUT12.1 COUT13.1 COUT14.1 COUT15.1 D6.1(C) E9.1(A) E44.1(A) J3.1(TP) Q1.5(D) Q2.5(D) Q5.5(D) Q6.5(D) Q9.5(D) Q10.5(D) Q13.5(D) Q14.5(D) Q17.5(D) Q18.5(D) R19.2
N18430581: C17.2 C40.2 L1.1 Q1.1(S) Q1.2(S) Q1.3(S) Q2.1(S) Q2.2(S) Q2.3(S) Q3.5(D) Q4.5(D) R72.1 U1.16(SW1)
N18430618: C40.1 R86.1 U1.15(TG1)
N18430621: Q1.4(G) Q2.4(G) R86.2
N18430651: Q3.4(G) Q4.4(G) R87.2
N18430663: R87.1 U1.11(BG1)
N18430719: C17.1 D1.1(C) R67.2
N18432657: C19.2 C38.2 L2.1 Q5.1(S) Q5.2(S) Q5.3(S) Q6.1(S) Q6.2(S) Q6.3(S) Q7.5(D) Q8.5(D) R73.1 U1.9(SW2)
N18432669: Q5.4(G) Q6.4(G) R88.2
N18432687: Q7.4(G) Q8.4(G) R89.2
N18432772: R89.1 U1.10(BG2)
N18432781: C19.1 D2.1(C) R66.2
N18432845: C38.1 R88.1 U1.8(TG2)
N18462849: R90.1 U1.1(BG4)
N18462895: C20.2 C39.2 L4.2 Q13.1(S) Q13.2(S) Q13.3(S) Q14.1(S) Q14.2(S) Q14.3(S) Q15.5(D) Q16.5(D) R75.1 U1.50(SW4)
N18462906: Q15.4(G) Q16.4(G) R90.2
N18462912: Q13.4(G) Q14.4(G) R93.2
N18462994: C20.1 D4.1(C) R64.2
N18463000: R64.1 U1.52(BST4)
N18463002: C39.1 R93.1 U1.51(TG4)
N18466723: C18.2 C41.2 L3.2 Q9.1(S) Q9.2(S) Q9.3(S) Q10.1(S) Q10.2(S) Q10.3(S) Q11.5(D) Q12.5(D) R74.1 U1.4(SW3)
N18466729: Q11.4(G) Q12.4(G) R92.2
N18466751: Q9.4(G) Q10.4(G) R91.2
N18466835: R92.1 U1.2(BG3)
N18466850: C18.1 D3.1(C) R65.2
N18466859: R65.1 U1.6(BST3)
N18466878: C41.1 R91.1 U1.5(TG3)
N18477908: Q21.3(S) U1.47(REGIS)
N18477910: Q21.1(G) U1.48(REGDRV)
N18477928: C7.2 R43.2 R81.1 U1.27(ILIM)
N18477935: C5.1 C56.2 R8.1 U1.18(TGSH)
N18477952: C5.2 C36.2 R123.2 U1.17(TGSR)
N18477956: C4.2 C51.1 R42.2 R105.2 R128.1 U1.35(ISP)
N18477960: C4.1 C48.1 R11.2 R105.1 R126.1 U1.34(ISN)
N18480103: C27.2 R7.2 U1.40(REGSNS)
N18481600: C6.2 E4.1(A) U1.33(IAMPP)
N18510074: R118.1 R119.2 U1.41(PHS3)
N18510086: C9.2 R116.1 R117.2 U1.24(PHS2)
N18510108: C8.2 R114.1 R115.2 U1.25(PHS1)
N18510127: R1.2 U1.26(RT/MS)
N18510138: E7.1(A) U1.20(CLK2)
N18510141: E12.1(A) U1.12(BGBUF)
N18510146: C55.2 R24.2 U1.23(SYNC)
N18510154: C54.2 R5.1 U1.22(BGSH)
N18510164: E11.1(A) U1.13(TGBUF)
N18515842: JP2.2 R2.2 R3.2 U1.31(~{SHDN})
N18516549: E34.1(A) R4.1 R124.2 U1.28(ENOUT)
N18580852: C35.2 JP3.2 U1.30(MODE)
N18602495: C23.2 R34.1 R130.1 TP1.1 U2.1(VBIAS)
N18635432: C36.1 C56.1 D6.2(A) D7.1(C) R121.2 U1.19(TGSL)
N18658123: C14.2 R17.2 R18.1 U2.15(VFB)
N18658279: R18.2 R19.1
N18658287: Q17.4(G) Q18.4(G) R99.1
N18658309: Q19.4(G) Q20.4(G) R100.1
N18677483: C1.2 R94.1 TP2.1 U1.49(VIN)
N18678326: R67.1 U1.14(BST1)
N18686895: R66.1 U1.7(BST2)
N18838508: R101.2 U2.20(BOOST)
N18965126: R50.1 R82.2 U2.7(FREQ)
N18965154: C15.1 R25.1 R51.2 U2.9(PLLIN/MODE)
N18965186: C25.1 U2.12(SS)
N18965204: E17.1(A) R16.1 U2.2(PGOOD)
N18965206: C57.1 D8.2(A) R9.1 R55.1 U2.11(RUN)
N18965324: C58.1 R20.2 U2.16(ITH)
N19043658: C53.1 R129.2 U2.23(EXTVCC)
N19044750: R112.1 R113.2 U2.17(OVMODE)
N19045378: C31.1 R20.1
N19047559: R104.1 R111.2 U2.3(ILIM)
N19104732: R8.2 R122.2
N19114134: C21.1 L6.2 U3.20(SW)
N19114180: R52.1 R61.2 U3.3(EN/UV)
N19114188: C21.2 U3.18(BST)
N19114208: C33.1 R54.2 U3.16(INTVCC)
N19114237: R26.1 R54.1 U3.7(SYNC/MODE)
N19114241: L6.1 U3.14(IND)
N19114260: R27.2 U3.8(RT)
N19114304: C34.1 U3.10(TR/SS)
N19114308: C26.2 R28.1 R29.2 U3.11(FB)
N19285489: E19.1(A) JP1.2
N19285551: JP1.4 R131.2
N19285683: JP1.1 JP1.3 JP1.5 R24.1

Not connected (* = marked no-connect by the designer): JP2 3; JP3 1; U1 42(NC); U2 4(NC) 6(NC); U3 5(PG) 6(NC) 9(NC) 13(NC) 15(NC)

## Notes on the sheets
sheet 1
- REVISION HISTORY
- ECO
- REV
- DESCRIPTION
- APPROVED
- DATE
- 3
- PRODUCTION
- VK
- 01-17-20
- [1]
- [1]
- 250kHz
- [1]
- [1]
- ASSY
- U1
- VAUX
- R10
- R28
- R34
- R130
- R131
- - A
- LT8561EUKG
- 11V
- OPT
- 78.7K
- OPT
- 2
- 150K
- - B
- LT8551EUKG
- 5.8V
- 0
- 162K
- 2
- OPT
- 0
- PRIMARY CONTROLLER
- 400kHz
- [1]
- MULTIPHASE BOOST CONVERTER EXPANDER
- WITH INTERNAL GATE DRIVERS
- 1.  UNLESS OTHERWISE SPECIFIED,
       ALL RESISTORS AND CAPACITORS ARE 0603
- 01-17-20
- NOTE: UNLESS OTHERWISE SPECIFIED
- - SEE QUICK START GUIDE
- 1.  ALL RESISTORS ARE IN OHMS, 0603.
       ALL CAPACITORS ARE IN MICROFARADS, 0603.
sheet 2
- [1]
- SPREAD FQ FOR
- DC2896A-A ONLY
- [1]
- SYNC
- SPREAD FQ
- PHS1
- FIX FQ
- STAGE SHED
- GND
- GND
- 250kHz
- FLOAT
- VCC
- PHS2
- GND
- TDPN SET
- VCC
- PHS3
- GND
- VCC
- MULTIPHASE BOOST CONVERTER EXPANDER
- WITH INTERNAL GATE DRIVERS
- Multiphase DC/DC converter expander interface
- 01-17-20
sheet 3
- [1]
- Multiphase DC/DC converter expander Phase 3 and 4
- ADITIONAL PARTS
- MULTIPHASE BOOST CONVERTER EXPANDER
- WITH INTERNAL GATE DRIVERS
- 01-17-20
- NOTE: UNLESS OTHERWISE SPECIFIED
- 1.  ALL RESISTORS ARE IN OHMS, 0603.
       ALL CAPACITORS ARE IN MICROFARADS, 0603.
sheet 4
- [1]
- MULTIPHASE BOOST CONVERTER EXPANDER
- WITH INTERNAL GATE DRIVERS
- Multiphase DC/DC converter expander Phase 1 and 2
- 01-17-20
